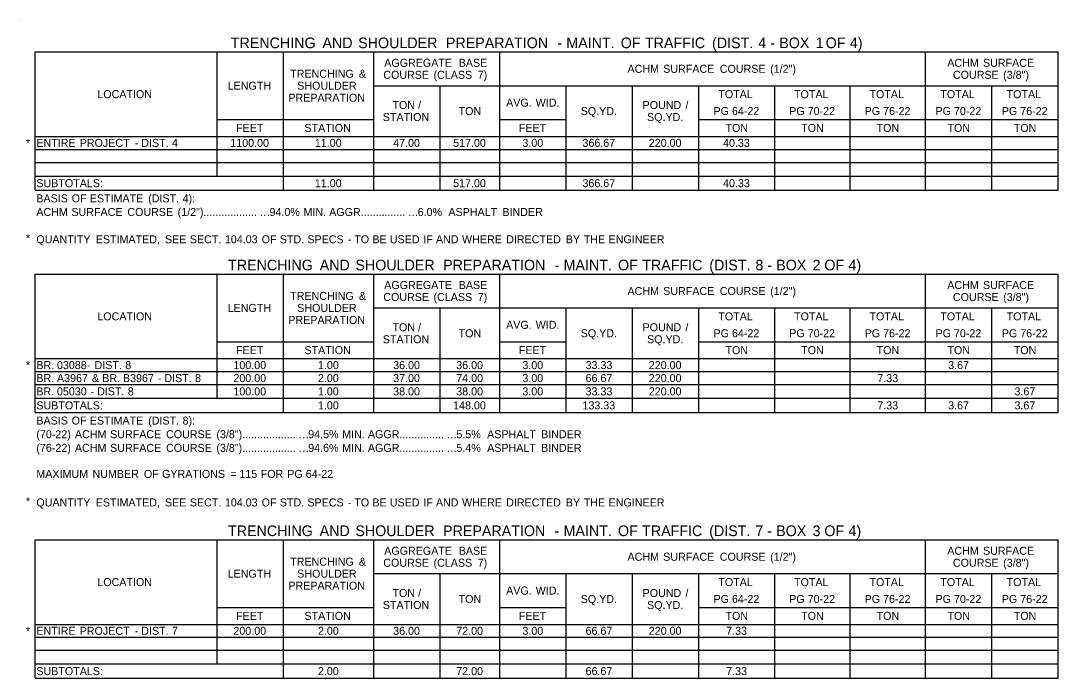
# Model space of a CAD drawing. Extents: x 540541 to 1930787, y -1948574 to 596640.
# Drawn here: x 552088 to 552866, y -1946541 to -1946047 of the extents above; entities that cross this region are included whole.
import ezdxf

# ---------------------------------------------------------------- set-up
doc = ezdxf.new("R2010")
doc.units = 0
doc.layers.add('Default', color=7, linetype='Continuous')
doc.layers.add('R_Border', color=7, linetype='Continuous')

msp = doc.modelspace()

# ---------------------------------------------------------------- linework, layer by layer
at = {"layer": 'Default'}
for p, q in [((552098.51, -1946070.75), (552865.84, -1946070.75)), ((552098.51, -1946070.75), (552865.84, -1946070.75)), ((552098.51, -1946174.59), (552098.51, -1946070.75)), ((552098.51, -1946174.59), (552098.51, -1946070.75)), ((552235.01, -1946163.86), (552235.01, -1946070.75)), ((552284.74, -1946174.59), (552284.74, -1946070.75)), ((552352.5, -1946174.59), (552352.5, -1946070.75)), ((552447.07, -1946174.59), (552447.07, -1946070.75)), ((552766.39, -1946174.59), (552766.39, -1946070.75)), ((552865.84, -1946174.59), (552865.84, -1946070.75)), ((552352.5, -1946096.1), (552865.84, -1946096.1)), ((552402.22, -1946174.59), (552402.22, -1946096.1)), ((552496.8, -1946174.59), (552496.8, -1946096.1)), ((552546.52, -1946174.59), (552546.52, -1946096.1)), ((552596.25, -1946174.59), (552596.25, -1946096.1)), ((552653.29, -1946174.59), (552653.29, -1946096.1)), ((552709.84, -1946174.59), (552709.84, -1946096.1)), ((552816.11, -1946174.59), (552816.11, -1946096.1)), ((552235.01, -1946121.45), (552352.5, -1946121.45)), ((552284.74, -1946174.59), (552284.74, -1946121.45)), ((552447.07, -1946121.45), (552496.8, -1946121.45)), ((552447.07, -1946134.13), (552447.07, -1946121.45)), ((552496.8, -1946163.86), (552496.8, -1946121.45)), ((552596.25, -1946121.45), (552865.84, -1946121.45)), ((552098.51, -1946134.13), (552352.5, -1946134.13)), ((552235.01, -1946163.86), (552235.01, -1946134.13)), ((552352.5, -1946134.13), (552496.8, -1946134.13)), ((552352.5, -1946143.88), (552352.5, -1946134.13)), ((552402.22, -1946163.86), (552402.22, -1946134.13)), ((552496.8, -1946134.13), (552865.84, -1946134.13)), ((552546.52, -1946163.86), (552546.52, -1946134.13)), ((552098.51, -1946143.88), (552352.5, -1946143.88)), ((552284.74, -1946143.88), (552352.5, -1946143.88)), ((552352.5, -1946143.88), (552865.84, -1946143.88)), ((552098.51, -1946153.63), (552865.84, -1946153.63)), ((552098.51, -1946163.86), (552284.74, -1946163.86)), ((552098.51, -1946163.86), (552235.01, -1946163.86)), ((552235.01, -1946163.86), (552865.84, -1946163.86)), ((552352.5, -1946163.86), (552865.84, -1946163.86)), ((552352.5, -1946174.59), (552352.5, -1946163.86)), ((552596.25, -1946174.59), (552596.25, -1946163.86)), ((552098.51, -1946174.59), (552865.84, -1946174.59)), ((552098.51, -1946237.48), (552865.84, -1946237.48)), ((552098.51, -1946237.48), (552865.84, -1946237.48)), ((552098.51, -1946341.31), (552098.51, -1946237.48)), ((552098.51, -1946341.31), (552098.51, -1946237.48)), ((552235.01, -1946330.59), (552235.01, -1946237.48)), ((552284.74, -1946341.31), (552284.74, -1946237.48)), ((552352.5, -1946341.31), (552352.5, -1946237.48)), ((552447.07, -1946341.31), (552447.07, -1946237.48)), ((552766.39, -1946341.31), (552766.39, -1946237.48)), ((552865.84, -1946341.31), (552865.84, -1946237.48)), ((552352.5, -1946262.83), (552865.84, -1946262.83)), ((552402.22, -1946341.31), (552402.22, -1946262.83)), ((552496.8, -1946341.31), (552496.8, -1946262.83)), ((552546.52, -1946341.31), (552546.52, -1946262.83)), ((552596.25, -1946341.31), (552596.25, -1946262.83)), ((552653.29, -1946341.31), (552653.29, -1946262.83)), ((552709.84, -1946341.31), (552709.84, -1946262.83)), ((552816.11, -1946341.31), (552816.11, -1946262.83)), ((552235.01, -1946288.18), (552352.5, -1946288.18)), ((552284.74, -1946341.31), (552284.74, -1946288.18)), ((552447.07, -1946288.18), (552496.8, -1946288.18)), ((552447.07, -1946300.85), (552447.07, -1946288.18)), ((552496.8, -1946330.59), (552496.8, -1946288.18)), ((552596.25, -1946288.18), (552865.84, -1946288.18)), ((552098.51, -1946300.85), (552352.5, -1946300.85)), ((552235.01, -1946330.59), (552235.01, -1946300.85)), ((552352.5, -1946300.85), (552496.8, -1946300.85)), ((552352.5, -1946341.31), (552352.5, -1946300.85)), ((552402.22, -1946330.59), (552402.22, -1946300.85)), ((552496.8, -1946300.85), (552865.84, -1946300.85)), ((552546.52, -1946330.59), (552546.52, -1946300.85)), ((552098.51, -1946310.6), (552865.84, -1946310.6)), ((552098.51, -1946320.35), (552865.84, -1946320.35)), ((552098.51, -1946330.59), (552865.84, -1946330.59)), ((552098.51, -1946330.59), (552865.84, -1946330.59)), ((552596.25, -1946341.31), (552596.25, -1946330.59)), ((552098.51, -1946341.31), (552865.84, -1946341.31)), ((552098.51, -1946436.86), (552865.84, -1946436.86)), ((552098.51, -1946436.86), (552865.84, -1946436.86)), ((552098.51, -1946540.7), (552098.51, -1946436.86)), ((552098.51, -1946540.7), (552098.51, -1946436.86)), ((552235.01, -1946529.98), (552235.01, -1946436.86)), ((552284.74, -1946540.7), (552284.74, -1946436.86)), ((552352.5, -1946540.7), (552352.5, -1946436.86)), ((552447.07, -1946540.7), (552447.07, -1946436.86)), ((552766.39, -1946540.7), (552766.39, -1946436.86)), ((552865.84, -1946540.7), (552865.84, -1946436.86)), ((552352.5, -1946462.21), (552865.84, -1946462.21)), ((552402.22, -1946540.7), (552402.22, -1946462.21)), ((552496.8, -1946540.7), (552496.8, -1946462.21)), ((552546.52, -1946540.7), (552546.52, -1946462.21)), ((552596.25, -1946540.7), (552596.25, -1946462.21)), ((552653.29, -1946540.7), (552653.29, -1946462.21)), ((552709.84, -1946540.7), (552709.84, -1946462.21)), ((552816.11, -1946540.7), (552816.11, -1946462.21)), ((552235.01, -1946487.56), (552352.5, -1946487.56)), ((552284.74, -1946540.7), (552284.74, -1946487.56)), ((552447.07, -1946487.56), (552496.8, -1946487.56)), ((552447.07, -1946500.24), (552447.07, -1946487.56)), ((552496.8, -1946529.98), (552496.8, -1946487.56)), ((552596.25, -1946487.56), (552865.84, -1946487.56)), ((552098.51, -1946500.24), (552352.5, -1946500.24)), ((552235.01, -1946529.98), (552235.01, -1946500.24)), ((552352.5, -1946500.24), (552496.8, -1946500.24)), ((552352.5, -1946509.99), (552352.5, -1946500.24)), ((552402.22, -1946529.98), (552402.22, -1946500.24)), ((552496.8, -1946500.24), (552865.84, -1946500.24)), ((552546.52, -1946529.98), (552546.52, -1946500.24)), ((552098.51, -1946509.99), (552865.84, -1946509.99)), ((552098.51, -1946519.74), (552865.84, -1946519.74)), ((552352.5, -1946540.7), (552352.5, -1946519.74)), ((552098.51, -1946529.98), (552865.84, -1946529.98)), ((552098.51, -1946529.98), (552865.84, -1946529.98)), ((552596.25, -1946540.7), (552596.25, -1946529.98)), ((552098.51, -1946540.7), (552865.84, -1946540.7))]:
    msp.add_line(p, q, dxfattribs=at)
at = {"layer": 'R_Border'}
msp.add_line((552087.79, -1946047.35), (552087.79, -1946047.35), dxfattribs=at)

# ---------------------------------------------------------------- texts
at = {"layer": 'Default'}
for s, height, p in [('TRENCHING', 8, (552245.31, -1946067.93)), (' AND', 8, (552311.08, -1946067.93)), (' SHOULDER', 8, (552337.85, -1946067.93)), (' PREPARATION', 8, (552403.63, -1946067.93)), (' -', 8, (552487.2, -1946067.93)), (' MAINT.', 8, (552493.95, -1946067.93)), (' OF', 8, (552534.78, -1946067.93)), (' TRAFFIC', 8, (552552.89, -1946067.93)), (' (DIST.', 8, (552603.23, -1946067.93)), (' 4', 8, (552637.85, -1946067.93)), (' -', 8, (552646.91, -1946067.93)), (' BOX', 8, (552653.65, -1946067.93)), (' 1', 8, (552680.97, -1946067.93)), (' OF', 8, (552688.48, -1946067.93)), (' 4)', 8, (552706.59, -1946067.93)), ('AGGREGATE', 6, (552360.37, -1946081.93)), (' BASE', 6, (552413.99, -1946081.93)), ('ACHM', 6, (552542.8, -1946086.43)), (' SURFACE', 6, (552567.35, -1946086.43)), (' COURSE', 6, (552609.79, -1946086.43)), (' (1/2")', 6, (552647.57, -1946086.43)), ('ACHM', 6, (552782.62, -1946081.93)), (' SURFACE', 6, (552807.17, -1946081.93)), ('TRENCHING', 6, (552289.83, -1946090.1)), (' &', 6, (552339.16, -1946090.1)), ('COURSE', 6, (552359.66, -1946090.93)), (' (CLASS', 6, (552395.12, -1946090.93)), (' 7)', 6, (552428.24, -1946090.93)), ('COURSE', 6, (552786.84, -1946090.93)), (' (3/8")', 6, (552822.29, -1946090.93)), ('LENGTH', 6, (552242.96, -1946099.1)), ('SHOULDER', 6, (552295.11, -1946099.1)), ('LOCATION', 6, (552145.21, -1946105.44)), ('PREPARATION', 6, (552288.44, -1946108.1)), ('TOTAL', 6, (552610.92, -1946105.44)), ('TOTAL', 6, (552667.72, -1946105.44)), ('TOTAL', 6, (552724.27, -1946105.44)), ('TOTAL', 6, (552777.4, -1946105.44)), ('TOTAL', 6, (552827.13, -1946105.44)), ('TON', 6, (552366.52, -1946113.61)), (' /', 6, (552383.54, -1946113.61)), ('TON', 6, (552416.14, -1946118.11)), ('AVG.', 6, (552451.79, -1946111.78)), (' WID.', 6, (552471.71, -1946111.78)), ('SQ.YD.', 6, (552507.74, -1946118.11)), ('POUND', 6, (552554.12, -1946113.61)), (' /', 6, (552583.99, -1946113.61)), ('PG', 6, (552607.3, -1946118.11)), (' 64-22', 6, (552618.9, -1946118.11)), ('PG', 6, (552664.09, -1946118.11)), (' 70-22', 6, (552675.7, -1946118.11)), ('PG', 6, (552720.64, -1946118.11)), (' 76-22', 6, (552732.25, -1946118.11)), ('PG', 6, (552773.78, -1946118.11)), (' 70-22', 6, (552785.38, -1946118.11)), ('PG', 6, (552823.5, -1946118.11)), (' 76-22', 6, (552835.11, -1946118.11)), ('STATION', 6, (552359.3, -1946122.61)), ('SQ.YD.', 6, (552557.47, -1946122.61)), ('FEET', 6, (552249.25, -1946130.79)), ('STATION', 6, (552300.56, -1946130.79)), ('FEET', 6, (552461.31, -1946130.79)), ('TON', 6, (552616.26, -1946130.79)), ('TON', 6, (552673.05, -1946130.79)), ('TON', 6, (552729.6, -1946130.79)), ('TON', 6, (552782.74, -1946130.79)), ('TON', 6, (552832.46, -1946130.79)), ('*', 6, (552091.67, -1946142)), ('ENTIRE', 6, (552099.49, -1946142)), (' PROJECT', 6, (552129.78, -1946142)), (' DIST.', 6, (552175.93, -1946142)), (' 4', 6, (552198.95, -1946142)), ('1100.00', 6, (552244.93, -1946142)), ('11.00', 6, (552308.34, -1946142)), ('47.00', 6, (552367.08, -1946142)), ('517.00', 6, (552412.04, -1946142)), ('3.00', 6, (552463.98, -1946142)), ('366.67', 6, (552509.04, -1946142)), ('220.00', 6, (552558.77, -1946142)), ('40.33', 6, (552614.47, -1946142)), (' -', 6, (552171.08, -1946142)), ('SUBTOTALS:', 6, (552099.49, -1946172.23)), ('11.00', 6, (552308.34, -1946172.23)), ('517.00', 6, (552412.04, -1946172.23)), ('366.67', 6, (552509.03, -1946172.23)), ('40.33', 6, (552614.47, -1946172.23)), ('BASIS', 6, (552099.49, -1946183.63)), (' OF', 6, (552123.75, -1946183.63)), (' ESTIMATE', 6, (552137.33, -1946183.63)), (' (DIST.', 6, (552181.14, -1946183.63)), (' 4):', 6, (552206.95, -1946183.63)), ('ACHM', 6, (552099.49, -1946193.86)), (' SURFACE', 6, (552123.54, -1946193.86)), (' COURSE', 6, (552165.49, -1946193.86)), (' (1/2")..................', 6, (552203.24, -1946193.86)), ('94.0%', 6, (552274.34, -1946193.86)), (' MIN.', 6, (552297.58, -1946193.86)), (' AGGR...............', 6, (552316.87, -1946193.86)), ('6.0%', 6, (552385.47, -1946193.86)), ('  ASPHALT', 6, (552404.05, -1946193.86)), (' BINDER', 6, (552446.75, -1946193.86)), ('…', 6, (552266.94, -1946193.86)), ('…', 6, (552378.07, -1946193.86)), ('*', 6, (552091.67, -1946213.42)), ('QUANTITY', 6, (552099.49, -1946214.34)), (' ESTIMATED,', 6, (552141.81, -1946214.34)), (' SEE', 6, (552193.7, -1946214.34)), (' SECT.', 6, (552212.36, -1946214.34)), (' 104.03', 6, (552238.65, -1946214.34)), (' OF', 6, (552266.23, -1946214.34)), (' STD.', 6, (552279.81, -1946214.34)), (' SPECS', 6, (552300.51, -1946214.34)), (' -', 6, (552330.82, -1946214.34)), (' TO', 6, (552335.68, -1946214.34)), (' BE', 6, (552349.27, -1946214.34)), (' USED', 6, (552362.34, -1946214.34)), (' IF', 6, (552387.51, -1946214.34)), (' AND', 6, (552396.91, -1946214.34)), (' WHERE', 6, (552416.49, -1946214.34)), (' DIRECTED', 6, (552449.58, -1946214.34)), (' BY', 6, (552494.31, -1946214.34)), (' THE', 6, (552507.76, -1946214.34)), (' ENGINEER', 6, (552526.41, -1946214.34)), ('TRENCHING', 8, (552243.25, -1946234.65)), (' AND', 8, (552309.03, -1946234.65)), (' SHOULDER', 8, (552335.79, -1946234.65)), (' PREPARATION', 8, (552401.57, -1946234.65)), (' MAINT.', 8, (552491.89, -1946234.65)), (' OF', 8, (552532.72, -1946234.65)), (' TRAFFIC', 8, (552550.83, -1946234.65)), (' (DIST.', 8, (552601.17, -1946234.65)), (' 8', 8, (552635.79, -1946234.65)), (' BOX', 8, (552651.35, -1946234.65)), (' 2', 8, (552678.67, -1946234.65)), (' OF', 8, (552687.43, -1946234.65)), (' 4)', 8, (552705.54, -1946234.65)), (' -', 8, (552485.15, -1946234.65)), (' -', 8, (552644.61, -1946234.65)), ('AGGREGATE', 6, (552360.37, -1946248.65)), (' BASE', 6, (552413.99, -1946248.65)), ('ACHM', 6, (552782.62, -1946248.65)), (' SURFACE', 6, (552807.17, -1946248.65)), ('TRENCHING', 6, (552289.83, -1946256.83)), (' &', 6, (552339.16, -1946256.83)), ('COURSE', 6, (552359.66, -1946257.65)), (' (CLASS', 6, (552395.12, -1946257.65)), (' 7)', 6, (552428.24, -1946257.65)), ('ACHM', 6, (552542.8, -1946253.15)), (' SURFACE', 6, (552567.35, -1946253.15)), (' COURSE', 6, (552609.79, -1946253.15)), (' (1/2")', 6, (552647.57, -1946253.15)), ('COURSE', 6, (552786.84, -1946257.65)), (' (3/8")', 6, (552822.29, -1946257.65)), ('LENGTH', 6, (552242.96, -1946265.83)), ('SHOULDER', 6, (552295.11, -1946265.83)), ('LOCATION', 6, (552145.21, -1946272.16)), ('TOTAL', 6, (552610.92, -1946272.16)), ('TOTAL', 6, (552667.72, -1946272.16)), ('TOTAL', 6, (552724.27, -1946272.16)), ('TOTAL', 6, (552777.4, -1946272.16)), ('TOTAL', 6, (552827.13, -1946272.16)), ('PREPARATION', 6, (552288.44, -1946274.83)), ('TON', 6, (552366.52, -1946280.34)), (' /', 6, (552383.54, -1946280.34)), ('AVG.', 6, (552451.79, -1946278.5)), (' WID.', 6, (552471.71, -1946278.5)), ('POUND', 6, (552554.12, -1946280.34)), (' /', 6, (552583.99, -1946280.34)), ('STATION', 6, (552359.3, -1946289.34)), ('TON', 6, (552416.14, -1946284.84)), ('SQ.YD.', 6, (552507.74, -1946284.84)), ('SQ.YD.', 6, (552557.47, -1946289.34)), ('PG', 6, (552607.3, -1946284.84)), (' 64-22', 6, (552618.9, -1946284.84)), ('PG', 6, (552664.09, -1946284.84)), (' 70-22', 6, (552675.7, -1946284.84)), ('PG', 6, (552720.64, -1946284.84)), (' 76-22', 6, (552732.25, -1946284.84)), ('PG', 6, (552773.78, -1946284.84)), (' 70-22', 6, (552785.38, -1946284.84)), ('PG', 6, (552823.5, -1946284.84)), (' 76-22', 6, (552835.11, -1946284.84)), ('FEET', 6, (552249.25, -1946297.51)), ('STATION', 6, (552300.56, -1946297.51)), ('FEET', 6, (552461.31, -1946297.51)), ('TON', 6, (552616.26, -1946297.51)), ('TON', 6, (552673.05, -1946297.51)), ('TON', 6, (552729.6, -1946297.51)), ('TON', 6, (552782.74, -1946297.51)), ('TON', 6, (552832.46, -1946297.51)), ('*', 6, (552091.67, -1946308.73)), ('BR.', 6, (552099.49, -1946308.73)), (' 03088-', 6, (552112.73, -1946308.73)), (' DIST.', 6, (552140.89, -1946308.73)), (' 8', 6, (552163.91, -1946308.73)), ('100.00', 6, (552247.26, -1946308.73)), ('1.00', 6, (552310.67, -1946308.73)), ('36.00', 6, (552367.08, -1946308.73)), ('36.00', 6, (552414.37, -1946308.73)), ('3.00', 6, (552463.98, -1946308.73)), ('33.33', 6, (552511.37, -1946308.73)), ('220.00', 6, (552558.77, -1946308.73)), ('3.67', 6, (552783.29, -1946308.73)), ('BR.', 6, (552099.49, -1946318.48)), (' A3967', 6, (552112.73, -1946318.48)), (' &', 6, (552138.91, -1946318.48)), (' BR.', 6, (552146.64, -1946318.48)), (' B3967', 6, (552162.21, -1946318.48)), (' DIST.', 6, (552193.25, -1946318.48)), (' 8', 6, (552216.27, -1946318.48)), ('200.00', 6, (552247.26, -1946318.48)), ('2.00', 6, (552310.67, -1946318.48)), ('37.00', 6, (552367.08, -1946318.48)), ('74.00', 6, (552414.37, -1946318.48)), ('3.00', 6, (552463.98, -1946318.48)), ('66.67', 6, (552511.37, -1946318.48)), ('220.00', 6, (552558.77, -1946318.48)), ('7.33', 6, (552730.15, -1946318.48)), ('BR.', 6, (552099.49, -1946328.47)), (' 05030', 6, (552112.73, -1946328.47)), (' DIST.', 6, (552142.81, -1946328.47)), (' 8', 6, (552165.83, -1946328.47)), (' -', 6, (552188.39, -1946318.48)), ('100.00', 6, (552247.26, -1946328.47)), ('1.00', 6, (552310.67, -1946328.47)), ('38.00', 6, (552367.08, -1946328.47)), ('38.00', 6, (552414.37, -1946328.47)), ('3.00', 6, (552463.98, -1946328.47)), ('33.33', 6, (552511.37, -1946328.47)), ('220.00', 6, (552558.77, -1946328.47)), ('3.67', 6, (552833.01, -1946328.47)), (' -', 6, (552137.96, -1946328.47)), ('SUBTOTALS:', 6, (552099.49, -1946338.95)), ('1.00', 6, (552310.67, -1946338.95)), ('148.00', 6, (552412.04, -1946338.95)), ('133.33', 6, (552509.03, -1946338.95)), ('7.33', 6, (552730.14, -1946338.95)), ('3.67', 6, (552783.28, -1946338.95)), ('3.67', 6, (552833.01, -1946338.95)), ('BASIS', 6, (552099.49, -1946350.35)), (' OF', 6, (552123.75, -1946350.35)), (' ESTIMATE', 6, (552137.33, -1946350.35)), (' (DIST.', 6, (552181.14, -1946350.35)), (' 8):', 6, (552206.95, -1946350.35)), ('(70-22)', 6, (552099.49, -1946360.59)), (' (3/8")..................', 6, (552232.27, -1946360.59)), (' ACHM', 6, (552126.19, -1946360.59)), (' SURFACE', 6, (552152.58, -1946360.59)), (' COURSE', 6, (552194.52, -1946360.59)), ('…', 6, (552295.97, -1946360.59)), ('94.5%', 6, (552303.37, -1946360.59)), (' MIN.', 6, (552326.61, -1946360.59)), (' AGGR...............', 6, (552345.9, -1946360.59)), ('…', 6, (552407.11, -1946360.59)), ('5.5%', 6, (552414.51, -1946360.59)), ('  ASPHALT', 6, (552433.09, -1946360.59)), (' BINDER', 6, (552475.78, -1946360.59)), ('(76-22)', 6, (552099.49, -1946370.83)), (' ACHM', 6, (552126.19, -1946370.83)), (' SURFACE', 6, (552152.58, -1946370.83)), (' COURSE', 6, (552194.52, -1946370.83)), (' (3/8")..................', 6, (552232.27, -1946370.83)), ('94.6%', 6, (552303.37, -1946370.83)), (' MIN.', 6, (552326.61, -1946370.83)), (' AGGR...............', 6, (552345.9, -1946370.83)), ('5.4%', 6, (552414.51, -1946370.83)), ('  ASPHALT', 6, (552433.09, -1946370.83)), (' BINDER', 6, (552475.78, -1946370.83)), ('…', 6, (552295.97, -1946370.83)), ('…', 6, (552407.11, -1946370.83)), ('MAXIMUM', 6, (552099.49, -1946390.38)), (' NUMBER', 6, (552139.37, -1946390.38)), (' OF', 6, (552177.92, -1946390.38)), (' GYRATIONS', 6, (552191.51, -1946390.38)), (' 115', 6, (552249.53, -1946390.38)), (' FOR', 6, (552265.51, -1946390.38)), (' PG', 6, (552285.42, -1946390.38)), (' 64-22', 6, (552299.33, -1946390.38)), (' =', 6, (552242.78, -1946390.38)), ('*', 6, (552091.67, -1946410.86)), ('QUANTITY', 6, (552099.49, -1946411.78)), (' ESTIMATED,', 6, (552141.81, -1946411.78)), (' SEE', 6, (552193.7, -1946411.78)), (' SECT.', 6, (552212.36, -1946411.78)), (' 104.03', 6, (552238.65, -1946411.78)), (' OF', 6, (552266.23, -1946411.78)), (' STD.', 6, (552279.81, -1946411.78)), (' SPECS', 6, (552300.51, -1946411.78)), (' TO', 6, (552335.68, -1946411.78)), (' BE', 6, (552349.27, -1946411.78)), (' USED', 6, (552362.34, -1946411.78)), (' IF', 6, (552387.51, -1946411.78)), (' AND', 6, (552396.91, -1946411.78)), (' WHERE', 6, (552416.49, -1946411.78)), (' DIRECTED', 6, (552449.58, -1946411.78)), (' BY', 6, (552494.31, -1946411.78)), (' THE', 6, (552507.76, -1946411.78)), (' ENGINEER', 6, (552526.41, -1946411.78)), (' -', 6, (552330.82, -1946411.78)), ('TRENCHING', 8, (552243.21, -1946434.04)), (' AND', 8, (552308.98, -1946434.04)), (' SHOULDER', 8, (552335.75, -1946434.04)), (' PREPARATION', 8, (552401.53, -1946434.04)), (' -', 8, (552485.1, -1946434.04)), (' MAINT.', 8, (552491.85, -1946434.04)), (' OF', 8, (552532.68, -1946434.04)), (' TRAFFIC', 8, (552550.79, -1946434.04)), (' (DIST.', 8, (552601.13, -1946434.04)), (' 7', 8, (552635.75, -1946434.04)), (' -', 8, (552644.57, -1946434.04)), (' BOX', 8, (552651.32, -1946434.04)), (' 3', 8, (552678.64, -1946434.04)), (' OF', 8, (552687.47, -1946434.04)), (' 4)', 8, (552705.58, -1946434.04)), ('AGGREGATE', 6, (552360.37, -1946448.04)), (' BASE', 6, (552413.99, -1946448.04)), ('ACHM', 6, (552542.8, -1946452.54)), (' SURFACE', 6, (552567.35, -1946452.54)), (' COURSE', 6, (552609.79, -1946452.54)), (' (1/2")', 6, (552647.57, -1946452.54)), ('ACHM', 6, (552782.62, -1946448.04)), (' SURFACE', 6, (552807.17, -1946448.04)), ('TRENCHING', 6, (552289.83, -1946456.21)), (' &', 6, (552339.16, -1946456.21)), ('COURSE', 6, (552359.66, -1946457.04)), (' (CLASS', 6, (552395.12, -1946457.04)), (' 7)', 6, (552428.24, -1946457.04)), ('COURSE', 6, (552786.84, -1946457.04)), (' (3/8")', 6, (552822.29, -1946457.04)), ('LENGTH', 6, (552242.96, -1946465.21)), ('SHOULDER', 6, (552295.11, -1946465.21)), ('LOCATION', 6, (552145.21, -1946471.55)), ('PREPARATION', 6, (552288.44, -1946474.21)), ('TOTAL', 6, (552610.92, -1946471.55)), ('TOTAL', 6, (552667.72, -1946471.55)), ('TOTAL', 6, (552724.27, -1946471.55)), ('TOTAL', 6, (552777.4, -1946471.55)), ('TOTAL', 6, (552827.13, -1946471.55)), ('TON', 6, (552366.52, -1946479.73)), (' /', 6, (552383.54, -1946479.73)), ('TON', 6, (552416.14, -1946484.23)), ('AVG.', 6, (552451.79, -1946477.89)), (' WID.', 6, (552471.71, -1946477.89)), ('SQ.YD.', 6, (552507.74, -1946484.23)), ('POUND', 6, (552554.12, -1946479.73)), (' /', 6, (552583.99, -1946479.73)), ('PG', 6, (552607.3, -1946484.23)), (' 64-22', 6, (552618.9, -1946484.23)), ('PG', 6, (552664.09, -1946484.23)), (' 70-22', 6, (552675.7, -1946484.23)), ('PG', 6, (552720.64, -1946484.23)), (' 76-22', 6, (552732.25, -1946484.23)), ('PG', 6, (552773.78, -1946484.23)), (' 70-22', 6, (552785.38, -1946484.23)), ('PG', 6, (552823.5, -1946484.23)), (' 76-22', 6, (552835.11, -1946484.23)), ('STATION', 6, (552359.3, -1946488.73)), ('SQ.YD.', 6, (552557.47, -1946488.73)), ('FEET', 6, (552249.25, -1946496.9)), ('STATION', 6, (552300.56, -1946496.9)), ('FEET', 6, (552461.31, -1946496.9)), ('TON', 6, (552616.26, -1946496.9)), ('TON', 6, (552673.05, -1946496.9)), ('TON', 6, (552729.6, -1946496.9)), ('TON', 6, (552782.74, -1946496.9)), ('TON', 6, (552832.46, -1946496.9)), ('*', 6, (552091.67, -1946508.11)), ('ENTIRE', 6, (552099.49, -1946508.11)), (' PROJECT', 6, (552129.78, -1946508.11)), (' DIST.', 6, (552175.93, -1946508.11)), (' 7', 6, (552198.95, -1946508.11)), ('200.00', 6, (552247.26, -1946508.11)), ('2.00', 6, (552310.67, -1946508.11)), ('36.00', 6, (552367.08, -1946508.11)), ('72.00', 6, (552414.37, -1946508.11)), ('3.00', 6, (552463.98, -1946508.11)), ('66.67', 6, (552511.37, -1946508.11)), ('220.00', 6, (552558.77, -1946508.11)), ('7.33', 6, (552616.8, -1946508.11)), (' -', 6, (552171.08, -1946508.11)), ('SUBTOTALS:', 6, (552099.49, -1946538.34)), ('2.00', 6, (552310.67, -1946538.34)), ('72.00', 6, (552414.37, -1946538.34)), ('66.67', 6, (552511.36, -1946538.34)), ('7.33', 6, (552616.8, -1946538.34))]:
    msp.add_text(s, height=height, dxfattribs=at).set_placement(p)

doc.saveas('drawing.dxf')
